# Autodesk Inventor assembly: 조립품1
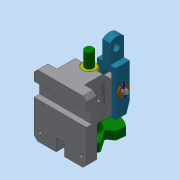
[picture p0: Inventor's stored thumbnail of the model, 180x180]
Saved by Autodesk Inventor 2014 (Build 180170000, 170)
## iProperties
Created: 2022-08
Part Number: 조립품1
Document SubType Name: Assembly
Designer: dg
Author: dg
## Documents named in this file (8)
- C:\Users\dg\Desktop\720806V1004\조립품1.iam
- C:\Users\dg\Desktop\720806V1004\본체.ipt
- C:\Users\dg\Desktop\720806V1004\부시.ipt
- C:\Users\dg\Desktop\720806V1004\분할축.ipt
- C:\Users\dg\Desktop\720806V1004\분할대.ipt
- C:\Users\dg\Desktop\720806V1004\와셔.ipt
- C:\Users\dg\Desktop\720806V1004\클레비스핀.ipt
- C:\Users\dg\Desktop\720806V1004\분할핀.ipt
